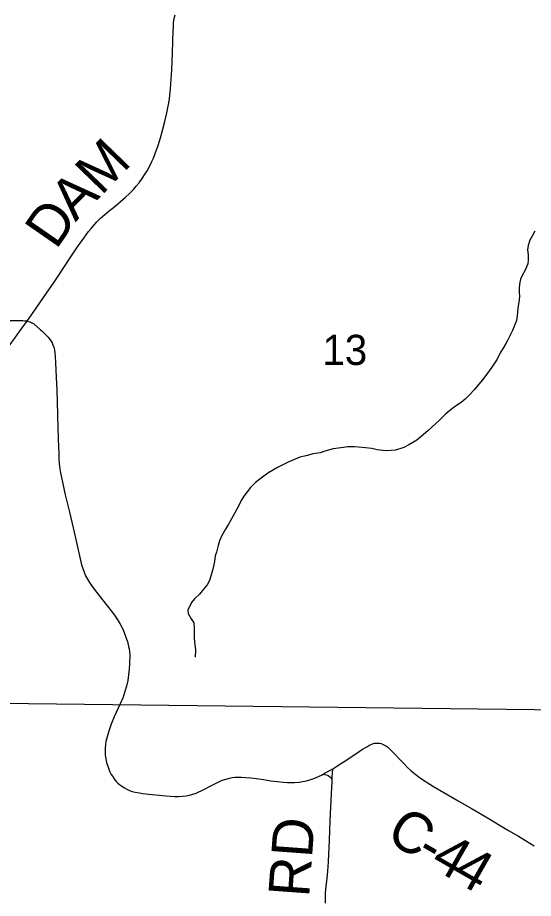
# Model space of a CAD drawing. Extents: x 0 to 34, y 0 to 22.
# Drawn here: x 6.594 to 7.311, y 14.622 to 15.844 of the extents above; entities that cross this region are included whole.
import ezdxf

# ---------------------------------------------------------------- set-up
doc = ezdxf.new("R2010")
doc.units = 0
for name, color, linetype in [('GM_X_Corporation', 7, 'Continuous'), ('GM_X_County_Road_Text', 7, 'Continuous'), ('GM_X_Interstate_Route', 7, 'Continuous'), ('GM_X_Major_Lake', 7, 'Continuous'), ('GM_X_Minor_Lake', 7, 'Continuous'), ('GM_X_Section', 7, 'Continuous'), ('GM_X_Township_Road_Text', 7, 'Continuous'), ('GM_X_Unincorporated_Text', 7, 'Continuous')]:
    doc.layers.add(name, color=color, linetype=linetype)

msp = doc.modelspace()

# ---------------------------------------------------------------- linework, layer by layer
at = {"layer": 'GM_X_Corporation'}
for points in [[(6.6077, 15.4229), (6.6096, 15.4256), (6.6191, 15.4393), (6.6354, 15.4631), (6.6441, 15.4753), (6.6527, 15.4881), (6.6676, 15.5107), (6.6777, 15.5258), (6.6864, 15.5382), (6.6931, 15.5472), (6.6966, 15.5516), (6.7016, 15.5574), (6.7046, 15.5607), (6.7098, 15.5657), (6.7154, 15.5707), (6.7216, 15.5758), (6.73, 15.5826), (6.7408, 15.5916), (6.7442, 15.5947), (6.7493, 15.5995), (6.7553, 15.6056), (6.7593, 15.61), (6.7633, 15.615), (6.7675, 15.6208), (6.7708, 15.6258), (6.7742, 15.6315), (6.7777, 15.6374), (6.781, 15.6444), (6.7831, 15.6488), (6.7862, 15.657), (6.7895, 15.6666), (6.7928, 15.6773), (6.7962, 15.6894), (6.7988, 15.6997), (6.8017, 15.7119), (6.8036, 15.721), (6.8052, 15.731), (6.8058, 15.7367), (6.8068, 15.7446), (6.8075, 15.7524), (6.8085, 15.7718), (6.8095, 15.7951), (6.8106, 15.8267), (6.8108, 15.8309), (6.8112, 15.8369), (6.812, 15.8428), (6.8131, 15.8481)], [(6.5452, 15.3343), (6.5495, 15.3413), (6.5548, 15.3499), (6.5578, 15.3549), (6.563, 15.3623), (6.5675, 15.3683), (6.5735, 15.3765), (6.5781, 15.3825), (6.583, 15.3891), (6.5864, 15.3936), (6.5904, 15.3992), (6.594, 15.404), (6.5973, 15.4086), (6.6007, 15.4135), (6.6049, 15.4191), (6.6077, 15.4229)], [(6.5841, 15.4236), (6.5999, 15.4237), (6.6017, 15.4236), (6.6039, 15.4234), (6.6064, 15.4231), (6.6077, 15.4229), (6.6094, 15.4225), (6.6116, 15.4218), (6.6134, 15.421), (6.6152, 15.42), (6.6168, 15.4189), (6.6259, 15.4112), (6.6284, 15.4089), (6.6346, 15.4029), (6.6368, 15.4004), (6.6393, 15.3973), (6.641, 15.3948), (6.6423, 15.3925), (6.6436, 15.3899), (6.6447, 15.3866), (6.6457, 15.383), (6.6462, 15.379), (6.6468, 15.3737), (6.6472, 15.3656), (6.6481, 15.3446), (6.6489, 15.327), (6.6493, 15.3118), (6.6498, 15.292), (6.6503, 15.2752), (6.6508, 15.2594), (6.6512, 15.2484), (6.6515, 15.2389), (6.6517, 15.231), (6.6521, 15.2256), (6.6527, 15.2204), (6.6541, 15.2121), (6.6572, 15.1969), (6.6606, 15.1816), (6.664, 15.1667), (6.6668, 15.1556), (6.6742, 15.1238), (6.6834, 15.0845), (6.6849, 15.0795), (6.6867, 15.0743), (6.6888, 15.0693), (6.6913, 15.0646), (6.6943, 15.0598), (6.6981, 15.0544), (6.7041, 15.0466), (6.7176, 15.0297), (6.7264, 15.0183), (6.7301, 15.0132), (6.7333, 15.0083), (6.7364, 15.003), (6.7391, 14.998), (6.7414, 14.9931), (6.7426, 14.9904), (6.7459, 14.9814), (6.7469, 14.9781), (6.7487, 14.9712), (6.7493, 14.9678), (6.7498, 14.9642), (6.7502, 14.9592), (6.7501, 14.9472), (6.7496, 14.9398), (6.7487, 14.9319), (6.7475, 14.9242), (6.7458, 14.9163), (6.7436, 14.9089), (6.741, 14.9008), (6.737, 14.8914), (6.7288, 14.8734), (6.7245, 14.8632), (6.722, 14.8565), (6.7206, 14.8525), (6.7178, 14.8424), (6.7171, 14.8394), (6.7165, 14.8347), (6.7161, 14.8304), (6.7159, 14.8258), (6.7161, 14.8213), (6.7166, 14.817), (6.7174, 14.8129), (6.7181, 14.8098), (6.7196, 14.8049), (6.721, 14.801), (6.7227, 14.7971), (6.7245, 14.7935), (6.7261, 14.791), (6.7285, 14.7875), (6.731, 14.7844), (6.7335, 14.7816), (6.7361, 14.7795), (6.7386, 14.7776), (6.7421, 14.7755), (6.7461, 14.7733), (6.7501, 14.7715), (6.7538, 14.7701), (6.7578, 14.769), (6.7638, 14.7679), (6.7686, 14.7672), (6.7768, 14.7664), (6.7909, 14.7649), (6.8006, 14.764), (6.8069, 14.7636), (6.8129, 14.7632), (6.8179, 14.7631), (6.8237, 14.7634), (6.8288, 14.764), (6.8332, 14.7648), (6.838, 14.7662), (6.8424, 14.7677), (6.8461, 14.7693), (6.8496, 14.771), (6.8675, 14.7801), (6.8741, 14.7834), (6.8786, 14.7855), (6.8836, 14.7871), (6.8887, 14.7884), (6.8926, 14.7892), (6.896, 14.7898), (6.9001, 14.79), (6.9052, 14.7898), (6.9116, 14.7894), (6.9185, 14.7887), (6.9264, 14.7878), (6.9358, 14.7866), (6.9461, 14.7849), (6.9554, 14.7837), (6.9634, 14.7829), (6.9694, 14.7825), (6.9748, 14.7822), (6.9789, 14.7824), (6.9854, 14.7829), (6.9903, 14.7836), (6.9959, 14.7848), (7.0003, 14.786), (7.0057, 14.7878), (7.0093, 14.7893), (7.0164, 14.7928), (7.0189, 14.7941), (7.0218, 14.7957), (7.0265, 14.7983), (7.0322, 14.8016), (7.0444, 14.8091), (7.0492, 14.8119), (7.0691, 14.8253), (7.0737, 14.8285), (7.0805, 14.8326), (7.0833, 14.8343), (7.0875, 14.8362), (7.0902, 14.8369), (7.0932, 14.8372), (7.0972, 14.8369), (7.0993, 14.8364), (7.1013, 14.8356), (7.1031, 14.8348), (7.1061, 14.8331), (7.1081, 14.8317), (7.1113, 14.8289), (7.1138, 14.8264), (7.1298, 14.8095), (7.1358, 14.8034), (7.1409, 14.7988), (7.1456, 14.7947), (7.1503, 14.7911), (7.1553, 14.7876), (7.1669, 14.78), (7.1721, 14.7768), (7.2065, 14.757), (7.2186, 14.7499), (7.226, 14.7458), (7.2503, 14.7316), (7.2626, 14.7241), (7.2764, 14.7158), (7.29, 14.7078), (7.3001, 14.7018), (7.3119, 14.6945)]]:
    msp.add_lwpolyline(points, dxfattribs=at)
at = {"layer": 'GM_X_Interstate_Route'}
for points in [[(7.0189, 14.7941), (7.0207, 14.7936), (7.0233, 14.7929), (7.0256, 14.792), (7.0275, 14.7909), (7.0292, 14.7893), (7.0314, 14.7866)], [(7.0223, 14.6147), (7.022, 14.6221), (7.0223, 14.6289), (7.0231, 14.6386), (7.0243, 14.6491), (7.0253, 14.6595), (7.0262, 14.6724), (7.0266, 14.6829), (7.0271, 14.6923), (7.0276, 14.7026), (7.0286, 14.7297), (7.0298, 14.758), (7.0309, 14.7757), (7.0312, 14.7833), (7.0314, 14.7866), (7.0316, 14.7908), (7.0318, 14.7954), (7.0322, 14.8016)]]:
    msp.add_lwpolyline(points, dxfattribs=at)
at = {"layer": 'GM_X_Minor_Lake'}
msp.add_lwpolyline([(7.5725, 15.8874), (7.5466, 14.8803), (6.5307, 14.8925), (6.553, 15.9139)], close=True, dxfattribs=at)
at = {"layer": 'GM_X_Township_Road_Text'}
for points in [[(7.3127, 15.5476), (7.3097, 15.5415), (7.306, 15.5353), (7.3035, 15.5277), (7.3028, 15.5216), (7.3037, 15.5147), (7.3038, 15.5079), (7.3031, 15.5022), (7.2994, 15.4937), (7.2954, 15.4861), (7.2932, 15.4811), (7.2914, 15.4742), (7.2911, 15.4681), (7.2912, 15.4628), (7.2916, 15.4575), (7.2913, 15.4525), (7.2903, 15.4464), (7.2892, 15.4411), (7.2886, 15.4342), (7.2872, 15.4239), (7.2821, 15.4097), (7.2747, 15.3959), (7.2722, 15.3909), (7.2688, 15.3852), (7.2648, 15.3787), (7.2607, 15.3698), (7.2533, 15.3591), (7.2422, 15.3437), (7.2288, 15.3275), (7.2228, 15.3209), (7.2161, 15.3147), (7.2105, 15.3101), (7.2026, 15.3046), (7.1947, 15.2988), (7.1884, 15.293), (7.1806, 15.2853), (7.1641, 15.2705), (7.1488, 15.2577), (7.1379, 15.2511), (7.1308, 15.2476), (7.1195, 15.2436), (7.1134, 15.2431), (7.1066, 15.2426), (7.0941, 15.2443), (7.0865, 15.2458), (7.0778, 15.2468), (7.0679, 15.2481), (7.0626, 15.2484), (7.0527, 15.2483), (7.0471, 15.2474), (7.0327, 15.2457), (7.021, 15.2425), (7.0146, 15.2401), (7.0044, 15.2384), (6.9973, 15.2364), (6.9867, 15.2339), (6.9701, 15.2272), (6.9555, 15.2198), (6.942, 15.2116), (6.9307, 15.2034), (6.9251, 15.1988)], [(6.9251, 15.1988), (6.918, 15.1918), (6.9087, 15.1798), (6.905, 15.1737), (6.9021, 15.1676), (6.8962, 15.1568), (6.8914, 15.1484), (6.8873, 15.1411), (6.8833, 15.1342), (6.8777, 15.1242), (6.8748, 15.1177), (6.873, 15.1116), (6.8705, 15.102), (6.869, 15.097), (6.868, 15.0894), (6.8655, 15.0783), (6.863, 15.0688), (6.8612, 15.0627), (6.8579, 15.0569), (6.8531, 15.0511), (6.8471, 15.0438), (6.84, 15.0372), (6.8359, 15.0322), (6.8308, 15.0218), (6.8312, 15.0169), (6.8355, 15.0094), (6.8394, 15.0041), (6.8398, 14.9965), (6.8397, 14.9828), (6.8401, 14.9775), (6.8414, 14.9661), (6.8411, 14.9562)]]:
    msp.add_lwpolyline(points, dxfattribs=at)
at = {"layer": 'GM_X_Unincorporated_Text'}
msp.add_lwpolyline([(6.5122, 14.1), (7.5285, 14.1), (7.5466, 14.8803), (6.5307, 14.8925)], close=True, dxfattribs=at)

# ---------------------------------------------------------------- texts
at = {"layer": 'GM_X_County_Road_Text'}
msp.add_text('13', height=0.04186, rotation=0, dxfattribs=at).set_placement((7.0178, 15.362))
at = {"layer": 'GM_X_Major_Lake'}
for s, rotation, p in [('M', 46.0022, (6.7106, 15.5961)), ('A', 45.1442, (6.6747, 15.56)), ('D', 55.2834, (6.6479, 15.5209)), ('C', 327.8039, (7.1038, 14.704)), ('-', 329.9361, (7.1453, 14.6779)), ('4', 330.1168, (7.1657, 14.6661)), ('4', 330.2074, (7.1961, 14.6486))]:
    msp.add_text(s, height=0.0568, rotation=rotation, dxfattribs=at).set_placement(p)
at = {"layer": 'GM_X_Section'}
msp.add_text('RD', height=0.05682, rotation=85.814, dxfattribs=at).set_placement((6.9993, 14.6222))

doc.saveas('drawing.dxf')
